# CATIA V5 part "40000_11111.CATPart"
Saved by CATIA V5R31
Part number: 40000_11111
Revision: 1
Nomenclature: Kunckle RH
Property "部品番号(A社)": "40000-11111"
Property "部品名称(A社)": "Kunckle RH"
Property "Version(A社)": "1"
Property "材質(A社)": "FCD700"
Bounding box of the stored display mesh (mm): x 126.565 to 340.614, y 897.639 to 1013.2, z 1313.857 to 1558.404
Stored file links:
  \\solize.local\damia\dept\DDE_Design\10_order\2305701_JAMA_変換検証STEP3_お手本モデル作成\work\04_ダイハツ_鋳造\10_CATIA_V5\231219_案bCATIAデータ\40000_11111.CATPart
  G:\BODY\BX\_K_PROJECT\610_3D単独図\02_検討\26_幾何公差設定\01_シャシ設部品\09_サンプルデータ見直し_43211_B1070\01_3D図面\KOUSEI\43211_B1070_J.CATPart
  G:\BODY\BX\_K_PROJECT\610_3D単独図\02_検討\79_自工会提出3D図面データ（ナックル改）\WORK_AA_AA_230720.CATPart
  G:\BODY\BX\_K_PROJECT\610_3D単独図\02_検討\79_自工会提出3D図面データ（ナックル改）\01_CATIA_DATA\PROPERTY_40000_11111.xls
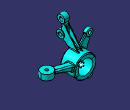
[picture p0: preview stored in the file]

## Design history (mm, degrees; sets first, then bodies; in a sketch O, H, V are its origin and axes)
Set1 "40000_11111"
  Line1 to Line3: stored without definition
  TriDim1
Body1 (main body)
